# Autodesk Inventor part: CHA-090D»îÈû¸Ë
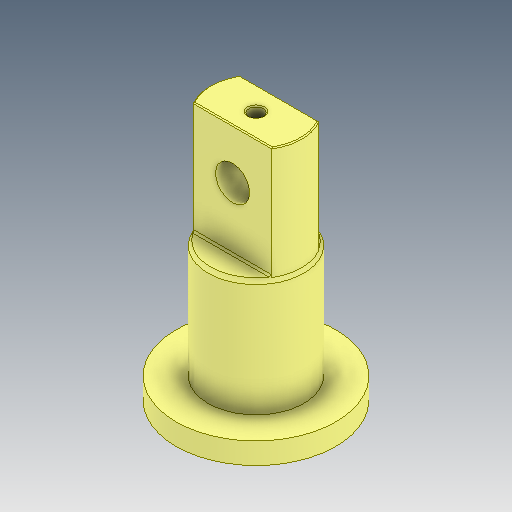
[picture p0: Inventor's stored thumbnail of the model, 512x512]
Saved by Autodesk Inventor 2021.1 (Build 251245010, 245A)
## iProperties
Created: 2021-05
Part Number: CHA-090D»îÈû¸Ë
Material: Ogólny
Document SubType Name: Modeling
Designer: user
Density: 1 g/cm^3
Appearance: Domyślna
Author: user
Revision Number: ÈÎºÎ
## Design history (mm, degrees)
feature "ÊäÈë1"
node "Bryła1"
